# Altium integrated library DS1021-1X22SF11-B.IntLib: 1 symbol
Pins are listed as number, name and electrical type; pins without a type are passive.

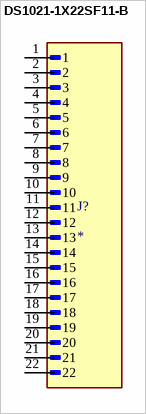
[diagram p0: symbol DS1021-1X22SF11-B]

## DS1021-1X22SF11-B
designator J?
22 position 2.54mm single row vertical pin header through hole; MPN: DS1021-1X22SF11-B; MANUFACTURER: Connfly
footprint CONNFLY_DS1021-1X22SF11-B
pins: 1, 2, 3, 4, 5, 6, 7, 8, 9, 10, 11, 12, 13, 14, 15, 16, 17, 18, 19, 20, 21, 22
